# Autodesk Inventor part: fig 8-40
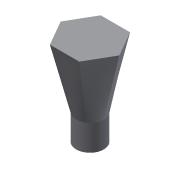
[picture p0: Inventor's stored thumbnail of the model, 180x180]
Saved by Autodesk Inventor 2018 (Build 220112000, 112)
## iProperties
Created: 2004-05
Part Number: fig 8-40
Document SubType Name: Modeling
Designer: CADCIM Technologies
Manufacturer: Standard
Standards Organization: Custom
Density: 1 g/cm^3
Material: Generic
Appearance: Default
Author: CADCIM Technologies
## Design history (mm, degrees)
sketch "Sketch1"
  geometry: C1 r 16.344 at (0, 0)
  constraints: 1 centre point
extrude "Extrusion1" new body sketch "Sketch1" distance "d0" = 30.75; taper "d1" = 0 deg
workplane "Work Plane1"
sketch "Sketch2"
  geometry: L1 (34.788, 0)-(17.394, -30.128); L2 (17.394, -30.128)-(-17.394, -30.128); L3 (-17.394, -30.128)-(-34.788, 0); L4 (-34.788, 0)-(-17.394, 30.128); L5 (-17.394, 30.128)-(17.394, 30.128); L6 (17.394, 30.128)-(34.788, 0); 2 further points
  constraints: 12 end point, 1 coincident, 12 other
loft "Loft2" sketch "Sketch2" dims "d7" = 0, "d8" = 90 deg, "d9" = 0, "d10" = 90 deg
  node "Edges2"
body "Solid1"
other parameters: "d2" = 75
